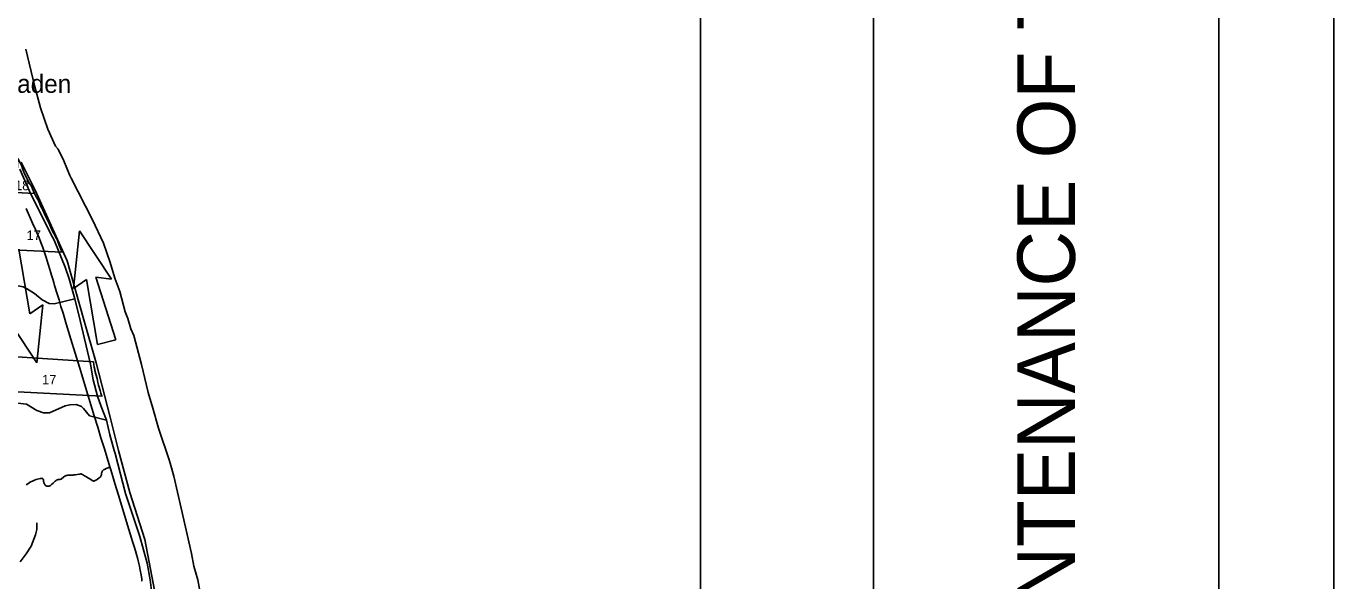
# Model space of a CAD drawing. Extents: x 396.2 to 468.4, y 232.6 to 279.1.
# Drawn here: x 424.52 to 430.2, y 267.39 to 269.8 of the extents above; entities that cross this region are included whole.
import ezdxf

# ---------------------------------------------------------------- set-up
doc = ezdxf.new("R2010")
doc.units = 0
for name, color, linetype in [('GM_X_Major_River', 7, 'Continuous'), ('GM_X_Minor_River', 7, 'Continuous'), ('GM_X_Section', 7, 'Continuous'), ('GM_X_Section_Text', 7, 'Continuous'), ('GM_X_State_Route', 7, 'Continuous'), ('GM_X_Township', 7, 'Continuous'), ('GM_X_Township_Road', 7, 'Continuous'), ('GM_X_Unincorporated_Text', 7, 'Continuous'), ('SH_Border', 7, 'Continuous'), ('SH_Cut_Line', 7, 'Continuous'), ('SH_Data', 7, 'Continuous'), ('TX_P_1', 7, 'Continuous')]:
    doc.layers.add(name, color=color, linetype=linetype)

msp = doc.modelspace()

# ---------------------------------------------------------------- linework, layer by layer
at = {"layer": 'GM_X_Major_River'}
for points in [[(424.9876, 268.4523), (424.975, 268.481), (424.9623, 268.5261), (424.9504, 268.556), (424.9268, 268.6431), (424.9061, 268.7014), (424.8861, 268.7703), (424.8561, 268.8535), (424.8083, 268.9557), (424.7154, 269.1357), (424.7101, 269.1481), (424.6848, 269.2117), (424.6595, 269.262), (424.6485, 269.276), (424.614, 269.3497), (424.5833, 269.4414), (424.5563, 269.5398), (424.5187, 269.6974)], [(424.4925, 269.1753), (424.5353, 269.0792), (424.6271, 268.8931), (424.6416, 268.8674), (424.6899, 268.749), (424.7068, 268.6983), (424.7319, 268.6115), (424.7547, 268.5172), (424.7996, 268.3282), (424.812, 268.26), (424.831, 268.1881), (424.8463, 268.1438), (424.869, 268.0844), (424.8833, 268.0203), (424.9033, 267.9526), (424.9068, 267.9389), (424.9524, 267.7651), (425.0146, 267.5792), (425.0467, 267.4622), (425.0592, 267.3898), (425.0651, 267.3444)], [(425.3062, 267.0759), (425.3036, 267.147), (425.2777, 267.3263), (425.266, 267.3896), (425.2494, 267.449), (425.2382, 267.5043), (425.1947, 267.7025), (425.1626, 267.8415), (425.1468, 267.8971), (425.1418, 267.9119), (425.0949, 268.0493), (425.0714, 268.1368), (425.0506, 268.2053), (425.0216, 268.3258), (424.9876, 268.4523)]]:
    msp.add_lwpolyline(points, dxfattribs=at)
at = {"layer": 'GM_X_Minor_River'}
for points in [[(424.7319, 268.6115), (424.642, 268.5903), (424.6197, 268.592), (424.5898, 268.6081), (424.557, 268.6346), (424.5226, 268.6572), (424.5068, 268.6638), (424.4628, 268.6724), (424.4356, 268.6806), (424.4144, 268.6925), (424.3945, 268.7154), (424.3757, 268.7459), (424.3451, 268.7685), (424.2835, 268.7952), (424.2407, 268.8068)], [(424.869, 268.0844), (424.796, 268.1037), (424.7697, 268.1357), (424.7616, 268.1432), (424.7373, 268.1519), (424.7112, 268.1516), (424.6895, 268.1466), (424.6217, 268.1157), (424.5964, 268.1157), (424.5665, 268.1269), (424.5223, 268.1542), (424.4839, 268.1584)], [(424.4948, 267.4684), (424.5205, 267.5036), (424.5422, 267.536), (424.5615, 267.5866), (424.5664, 267.6092), (424.5668, 267.635), (424.5661, 267.6374)]]:
    msp.add_lwpolyline(points, dxfattribs=at)
at = {"layer": 'GM_X_Section'}
for points in [[(424.4792, 269.138), (424.4839, 269.2225), (424.4939, 269.2029), (424.5011, 269.1889), (424.5049, 269.1787), (424.5092, 269.167), (424.5134, 269.1556), (424.5229, 269.1363), (424.5244, 269.1329), (424.5309, 269.1204), (424.5389, 269.108), (424.5431, 269.1015), (424.5477, 269.0906), (424.5523, 269.08), (424.5567, 269.0696), (424.4757, 269.0735)], [(424.5567, 269.0696), (424.566, 269.0523), (424.5699, 269.046), (424.5702, 269.0455), (424.5736, 269.0387), (424.5847, 269.0138), (424.5885, 269.0054), (424.5923, 268.9975), (424.6034, 268.974), (424.6168, 268.9472), (424.6324, 268.9112), (424.6408, 268.8957), (424.65, 268.8787), (424.6546, 268.8697), (424.6584, 268.8613), (424.666, 268.8409), (424.6725, 268.8239), (424.6763, 268.815), (424.4621, 268.825), (424.4757, 269.0735)], [(424.4367, 268.3619), (424.813, 268.3381), (424.8141, 268.3265), (424.816, 268.3147), (424.8183, 268.3049), (424.8191, 268.3004), (424.8233, 268.2845), (424.8294, 268.2652), (424.8321, 268.2474), (424.8345, 268.236), (424.8421, 268.2129), (424.8456, 268.2019), (424.8498, 268.1886), (424.4284, 268.2109)]]:
    msp.add_lwpolyline(points, close=True, dxfattribs=at)
at = {"layer": 'GM_X_State_Route'}
for points in [[(424.5484, 268.9411), (424.5392, 268.9615), (424.529, 268.9846), (424.5202, 269.0046)], [(425.0236, 267.3839), (425.0224, 267.3935), (425.0197, 267.4119), (425.0163, 267.4321), (425.0126, 267.4501), (425.0088, 267.4673), (425.0041, 267.4858), (425, 267.5001), (424.9951, 267.5167), (424.9893, 267.5359), (424.9828, 267.5572), (424.9728, 267.5898), (424.9612, 267.6278), (424.949, 267.6676), (424.9215, 267.758), (424.9062, 267.8085), (424.8968, 267.8394), (424.8881, 267.868), (424.8842, 267.8808), (424.8604, 267.9593), (424.8456, 268.0073), (424.8316, 268.0533), (424.8165, 268.1028), (424.8062, 268.1371), (424.7989, 268.1607), (424.7875, 268.1982), (424.7624, 268.2808), (424.7534, 268.3105), (424.7448, 268.3384), (424.7337, 268.3753), (424.7147, 268.4371), (424.6945, 268.5037), (424.6807, 268.5488), (424.6717, 268.5786), (424.6633, 268.6072), (424.655, 268.6338), (424.644, 268.6701), (424.6401, 268.6832), (424.6347, 268.701), (424.6307, 268.714), (424.6274, 268.7247), (424.623, 268.739), (424.6158, 268.7628), (424.6069, 268.791), (424.6, 268.8129), (424.5924, 268.8355), (424.5848, 268.8561), (424.5767, 268.8763), (424.57, 268.8923), (424.5612, 268.9128), (424.5484, 268.9411)]]:
    msp.add_lwpolyline(points, dxfattribs=at)
at = {"layer": 'GM_X_Township'}
msp.add_lwpolyline([(424.4986, 269.2054), (424.5598, 269.0842), (424.6989, 268.7768), (424.7711, 268.5199), (424.8244, 268.3342), (424.8848, 268.0973), (424.9219, 267.9518), (424.9706, 267.7703), (425.036, 267.5657), (425.0912, 267.2773)], dxfattribs=at)
at = {"layer": 'GM_X_Township_Road'}
msp.add_lwpolyline([(424.5206, 267.8037), (424.527, 267.808), (424.5335, 267.812), (424.5398, 267.8158), (424.5485, 267.8199), (424.556, 267.8235), (424.5643, 267.8265), (424.5702, 267.8283), (424.5761, 267.8299), (424.5815, 267.8311), (424.5857, 267.8315), (424.5896, 267.8316), (424.5919, 267.8311), (424.5935, 267.8297), (424.5947, 267.8278), (424.5951, 267.8239), (424.5955, 267.8203), (424.5963, 267.8172), (424.5969, 267.8154), (424.5979, 267.8115), (424.5985, 267.8096), (424.5995, 267.8076), (424.6006, 267.8056), (424.6019, 267.804), (424.6031, 267.8023), (424.605, 267.8002), (424.6072, 267.7986), (424.6082, 267.798), (424.6097, 267.7975), (424.618, 267.7968), (424.6194, 267.7971), (424.6209, 267.7976), (424.6234, 267.799), (424.6258, 267.8008), (424.6287, 267.8029), (424.6327, 267.8067), (424.6372, 267.8109), (424.6403, 267.8141), (424.6434, 267.817), (424.6471, 267.8198), (424.6511, 267.8226), (424.6543, 267.8243), (424.6573, 267.8256), (424.6589, 267.826), (424.6613, 267.8264), (424.668, 267.8269), (424.6703, 267.8276), (424.6724, 267.8286), (424.6841, 267.8374), (424.6891, 267.8413), (424.6909, 267.8424), (424.6927, 267.8432), (424.6954, 267.8442), (424.698, 267.8445), (424.7007, 267.8446), (424.7086, 267.8448), (424.7182, 267.845), (424.723, 267.8456), (424.7282, 267.8464), (424.7345, 267.8474), (424.7418, 267.8483), (424.753, 267.8501), (424.7573, 267.8507), (424.7588, 267.8508), (424.7602, 267.8506), (424.7616, 267.8501), (424.7653, 267.848), (424.7738, 267.8427), (424.7793, 267.8393), (424.7844, 267.8361), (424.8012, 267.826), (424.8068, 267.8228), (424.8095, 267.8212), (424.8116, 267.8204), (424.8138, 267.8199), (424.8157, 267.8199), (424.8181, 267.8204), (424.8233, 267.8232), (424.8284, 267.8263), (424.838, 267.8336), (424.8415, 267.8363), (424.8431, 267.8381), (424.8447, 267.8403), (424.8462, 267.8427), (424.8466, 267.8438), (424.8472, 267.8461), (424.8475, 267.8483), (424.8479, 267.8523), (424.8483, 267.8547), (424.8488, 267.8569), (424.8497, 267.8593), (424.851, 267.8619), (424.8523, 267.8642), (424.8541, 267.8663), (424.8562, 267.8678), (424.8585, 267.8692), (424.8613, 267.8706), (424.868, 267.8738), (424.8764, 267.8775), (424.8842, 267.8808)], dxfattribs=at)
at = {"layer": 'SH_Border'}
msp.add_line((428.2027, 257.6206), (428.2027, 278.6206), dxfattribs=at)
msp.add_lwpolyline([(397.7027, 278.6206), (429.7027, 278.6206), (429.7027, 257.6206), (397.7027, 257.6206)], close=True, dxfattribs=at)
at = {"layer": 'SH_Cut_Line'}
msp.add_lwpolyline([(396.2027, 257.1206), (430.2027, 257.1206), (430.2027, 279.1206), (396.2027, 279.1206)], close=True, dxfattribs=at)
msp.add_lwpolyline([(425.0912, 267.2773), (425.036, 267.5657), (424.9706, 267.7703), (424.9219, 267.9518), (424.8848, 268.0973), (424.8244, 268.3342), (424.7711, 268.5199), (424.6989, 268.7768), (424.5598, 269.0842), (424.4986, 269.2054)], dxfattribs=at)
at = {"layer": 'TX_P_1'}
for p, q in [((427.4513, 277.8582), (427.4513, 264.2582)), ((424.7258, 268.6564), (424.7527, 268.9081)), ((424.7527, 268.9081), (424.8915, 268.697)), ((424.4888, 268.8284), (424.5363, 268.5459)), ((424.7827, 268.6965), (424.7258, 268.6564)), ((424.8308, 268.4138), (424.7827, 268.6965)), ((424.8915, 268.697), (424.8227, 268.7062)), ((424.8227, 268.7062), (424.9097, 268.4331)), ((424.5665, 268.3343), (424.4276, 268.5454)), ((424.5363, 268.5459), (424.5934, 268.5856)), ((424.5934, 268.5856), (424.5665, 268.3343)), ((424.9097, 268.4331), (424.8308, 268.4138))]:
    msp.add_line(p, q, dxfattribs=at)

# ---------------------------------------------------------------- texts
at = {"layer": 'GM_X_Section_Text'}
for s, p in [('18', (424.4721, 269.084)), ('17', (424.5221, 268.867)), ('17', (424.5896, 268.2395))]:
    msp.add_text(s, height=0.04186, rotation=0, dxfattribs=at).set_placement(p)
at = {"layer": 'GM_X_Unincorporated_Text'}
msp.add_text('Bladen', height=0.07898, rotation=0, dxfattribs=at).set_placement((424.3875, 269.5072))
at = {"layer": 'SH_Data'}
msp.add_text('MAINTENANCE OF TRAFFIC (GAL-218-4.81)', height=0.25, rotation=90, dxfattribs=at).set_placement((429.0777, 266.6964))

doc.saveas('drawing.dxf')
